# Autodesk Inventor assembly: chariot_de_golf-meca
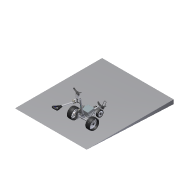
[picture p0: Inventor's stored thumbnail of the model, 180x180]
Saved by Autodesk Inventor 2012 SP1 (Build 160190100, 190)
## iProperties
Created: 2011-01
Part Number: chariot_de_golf-meca
Document SubType Name: Assembly
Designer: eric
Norme de conversion: STEP AP214IS
Nom du fichier: chariot_de_golf.STEP
Préprocesseur: SolidWorks 2007
Postprocesseur: Build: 342, Release: 2008 SP3 - Date: Tue 05/27/2008
Unités envoyées: MILLIMETERS
Incertitude: 1e-05
Author: eric
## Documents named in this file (6)
- D:\Cours\Inventor salle SI\chariot_de_golf_2008\chariot_de_golf_trolem\chariot_de_golf-meca.iam
- D:\Cours\Inventor salle SI\chariot_de_golf_2008\chariot_de_golf_trolem\Chassis.iam
- D:\Cours\Inventor salle SI\chariot_de_golf_2008\chariot_de_golf_trolem\essieu_avant.iam
- D:\Cours\Inventor salle SI\chariot_de_golf_2008\chariot_de_golf_trolem\essieu_arriere.iam
- D:\Cours\Inventor salle SI\chariot_de_golf_2008\chariot_de_golf_trolem\rotor moteur.iam
- D:\Cours\Inventor salle SI\chariot_de_golf_2008\chariot_de_golf_trolem\Sol-2.ipt
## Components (5 placed, 5 different names)
1. Chassis:1 [sub-assembly] — Logement:1, Logement:2, pilotage du moteur, Logement:3, Affleurement:2, Placage:1
2. essieu_avant:1 [sub-assembly] — Tangente:1, Logement:3, Tangente:3, Affleurement:3, Placage:1
3. essieu_arriere:1 [sub-assembly] — Logement:2, Tangente:2
4. rotor moteur:1 [sub-assembly] — Logement:1, pilotage du moteur
5. Sol-2:1 — Affleurement:1, Tangente:1, Tangente:2, Affleurement:2, Tangente:3, Affleurement:3
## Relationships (11: Insert 3, Flush 3, Tangent 3, Angle 1, Mate 1)
- Logement:1 [Insert]: Chassis:1 ↔ rotor moteur:1
- Logement:2 [Insert]: Chassis:1 ↔ essieu_arriere:1
- pilotage du moteur [Angle]: Chassis:1 ↔ rotor moteur:1
- Affleurement:1 [Flush]: Sol-2:1
- Tangente:1: essieu_avant:1 ↔ Sol-2:1
- Logement:3 [Insert]: Chassis:1 ↔ essieu_avant:1
- Tangente:2: essieu_arriere:1 ↔ Sol-2:1
- Affleurement:2 [Flush]: Chassis:1 ↔ Sol-2:1
- Tangente:3: essieu_avant:1 ↔ Sol-2:1
- Affleurement:3 [Flush]: essieu_avant:1 ↔ Sol-2:1
- Placage:1 [Mate]: Chassis:1 ↔ essieu_avant:1
